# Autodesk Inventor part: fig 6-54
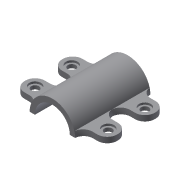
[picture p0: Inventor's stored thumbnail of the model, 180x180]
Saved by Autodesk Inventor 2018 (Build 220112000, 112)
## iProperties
Created: 2004-05
Part Number: fig 6-54
Document SubType Name: Modeling
Designer: CADCIM Technologies
Manufacturer: Standard
Standards Organization: Custom
Density: 1 g/cm^3
Material: Generic
Appearance: Default
Author: CADCIM Technologies
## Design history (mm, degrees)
node "Sketch1"
sketch "Sketch2"
  geometry: L1 (23.378, 0)-(17.996, 0); L2 (-17.996, 0)-(-23.378, 0); A1 r 23.378 centre (0, 0) between (23.378, 0) and (-23.378, 0); A2 r 17.996 centre (0, 0) between (17.996, 0) and (-17.996, 0)
  constraints: 4 end point, 4 point on circle, 2 centre point, 1 collinear, 1 horizontal
extrude "Extrusion1" new body sketch "Sketch2" stored distance "d0" = 38.75; taper "d1" = 0 deg
sketch "Sketch3"
  geometry: L1 (23.378, 0)-(17.996, 0); L2 (-17.996, 0)-(-23.378, 0) reference; L3 (-23.378, 0)-(-47.662, 0); L4 (-47.662, 0)-(-47.662, 5.722); L5 (-47.662, 5.722)-(-22.667, 5.722); A1 r 17.996 centre (0, 0) between (17.996, 0) and (-17.996, 0) reference; A2 r 23.378 centre (0, 0) between (23.378, 0) and (-23.378, 0) reference; 1 further point
  constraints: 10 end point, 5 point on circle, 2 centre point, 1 collinear, 1 horizontal, 1 midpoint, 1 parallel, 1 perpendicular, 3 other
extrude "Extrusion2" join sketch "Sketch3" stored distance "d2" = 21; taper "d3" = 0 deg
fillet "Fillet1" dims "d4" = 10
hole "Hole1" diameter "d7" = 8; stored, may be unused: countersink angle "d11" = 90 deg, drill point angle "d13" = 118 deg; dims "d5" = 10, "d6" = 10, "d8" = 6, "d9" = 12, "d10" = 2, "d12" = 12
fillet "Fillet2" dims "d14" = 9.5
mirror "Mirror1"
mirror "Mirror2"
body "Solid1"
